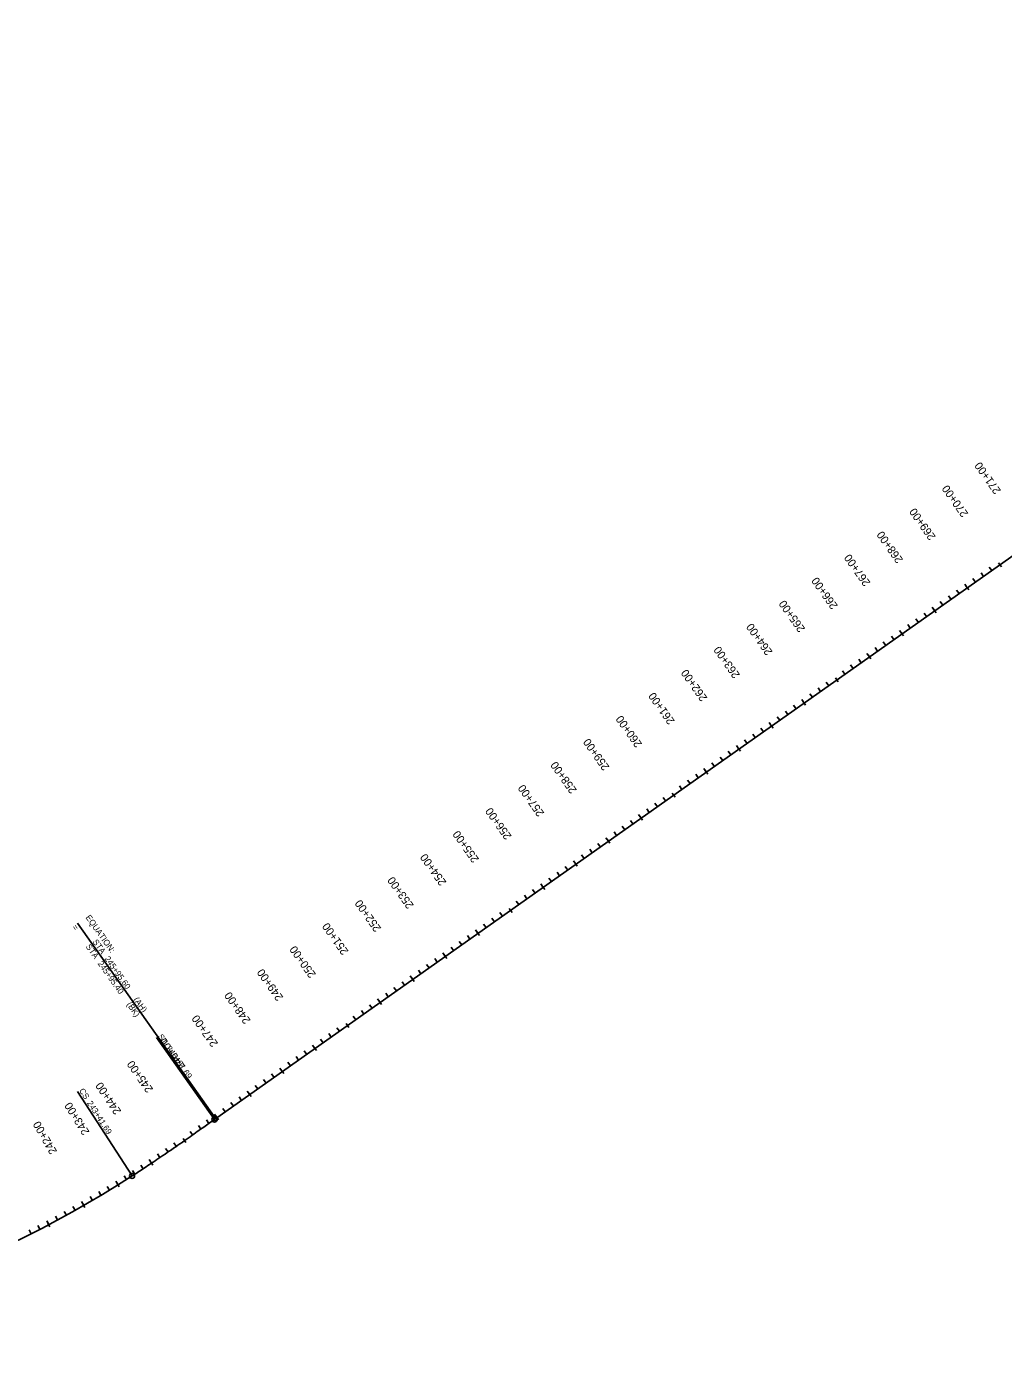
# Model space of a CAD drawing. Extents: x 22693007 to 22771804, y 6223023 to 6251673.
# Drawn here: x 22702871 to 22705317, y 6231587 to 6234910 of the extents above; entities that cross this region are included whole.
import ezdxf

# ---------------------------------------------------------------- set-up
doc = ezdxf.new("R2010")
doc.units = 0
for name, color, linetype in [('Default', 7, 'Continuous'), ('Draft_2', 7, 'Continuous'), ('NamedBoundary', 7, 'Continuous'), ('SheetBorder', 7, 'Continuous'), ('TextAlignment', 7, 'Continuous')]:
    doc.layers.add(name, color=color, linetype=linetype)

msp = doc.modelspace()

# ---------------------------------------------------------------- linework, layer by layer
at = {"layer": 'Default'}
msp.add_line((22703341, 6232172.5), (22707216.1, 6234910.4), dxfattribs=at)
msp.add_arc((22701585.2, 6234441), 2865, 274.9322, 302.7427, dxfattribs=at)
msp.add_open_spline([(22703134.8, 6232031.3), (22703143.6, 6232036.9), (22703161, 6232048.3), (22703195.7, 6232071.3), (22703238.7, 6232100.7), (22703281.4, 6232130.5), (22703315.5, 6232154.5), (22703332.5, 6232166.5), (22703341, 6232172.5)], degree=3, dxfattribs=at)
at = {"layer": 'Draft_2'}
for p, q in [((22705304.2, 6233567.1), (22705311.3, 6233557.1)), ((22705226.1, 6233504.4), (22705219.8, 6233513.3)), ((22705144.4, 6233446.7), (22705138.1, 6233455.6)), ((22705062.8, 6233389), (22705056.5, 6233397.9)), ((22704981.1, 6233331.3), (22704974.8, 6233340.2)), ((22704895.9, 6233278.6), (22704902.9, 6233268.6)), ((22704817.7, 6233215.9), (22704811.4, 6233224.8)), ((22704736.1, 6233158.2), (22704729.8, 6233167.1)), ((22704654.4, 6233100.5), (22704648.1, 6233109.4)), ((22704572.7, 6233042.8), (22704566.4, 6233051.7)), ((22704487.5, 6232990.1), (22704494.6, 6232980.1)), ((22704409.4, 6232927.4), (22704403.1, 6232936.3)), ((22704327.7, 6232869.6), (22704321.4, 6232878.6)), ((22704246, 6232811.9), (22704239.7, 6232820.9)), ((22704164.4, 6232754.2), (22704158.1, 6232763.2)), ((22704079.2, 6232701.5), (22704086.2, 6232691.5)), ((22704001, 6232638.8), (22703994.7, 6232647.7)), ((22703919.4, 6232581.1), (22703913.1, 6232590)), ((22703837.7, 6232523.4), (22703831.4, 6232532.3)), ((22703756, 6232465.7), (22703749.7, 6232474.6)), ((22703670.8, 6232413), (22703677.9, 6232403)), ((22703592.7, 6232350.3), (22703586.4, 6232359.2)), ((22703511, 6232292.6), (22703504.7, 6232301.5)), ((22703429.3, 6232234.9), (22703423, 6232243.8)), ((22703347.7, 6232177.2), (22703341.4, 6232186.1)), ((22703262.5, 6232124.8), (22703269.5, 6232114.7)), ((22703183.5, 6232063.3), (22703177.5, 6232072.3)), ((22703099.6, 6232009), (22703093.8, 6232018.2)), ((22703013.8, 6231957.6), (22703008.3, 6231967.1)), ((22702926.2, 6231909.3), (22702921.1, 6231918.9))]:
    msp.add_line(p, q, dxfattribs=at)
at = {"layer": 'NamedBoundary'}
msp.add_line((22703341, 6232172.5), (22707216.1, 6234910.4), dxfattribs=at)
msp.add_arc((22701585.2, 6234441), 2865, 274.9322, 302.7427, dxfattribs=at)
msp.add_open_spline([(22703134.8, 6232031.3), (22703143.6, 6232036.9), (22703161, 6232048.3), (22703195.7, 6232071.3), (22703238.7, 6232100.7), (22703281.4, 6232130.5), (22703315.5, 6232154.5), (22703332.5, 6232166.5), (22703341, 6232172.5)], degree=3, dxfattribs=at)
at = {"layer": 'SheetBorder'}
for p, q in [((22705266.9, 6233533.2), (22705260.6, 6233542.2)), ((22705287.4, 6233547.7), (22705281.1, 6233556.6)), ((22705304.2, 6233567.1), (22705311.3, 6233557.1)), ((22705222.6, 6233509.4), (22705229.6, 6233499.4)), ((22705246.5, 6233518.8), (22705240.2, 6233527.7)), ((22705185.3, 6233475.5), (22705179, 6233484.5)), ((22705205.7, 6233490), (22705199.4, 6233498.9)), ((22705124, 6233432.3), (22705117.7, 6233441.2)), ((22705140.9, 6233451.7), (22705148, 6233441.7)), ((22705164.8, 6233461.1), (22705158.5, 6233470)), ((22705083.2, 6233403.4), (22705076.9, 6233412.3)), ((22705103.6, 6233417.8), (22705097.3, 6233426.8)), ((22705042.3, 6233374.6), (22705036, 6233383.5)), ((22705059.2, 6233394), (22705066.3, 6233384)), ((22705001.5, 6233345.7), (22704995.2, 6233354.6)), ((22705021.9, 6233360.1), (22705015.6, 6233369)), ((22704940.3, 6233302.4), (22704933.9, 6233311.3)), ((22704960.7, 6233316.9), (22704954.4, 6233325.8)), ((22704977.6, 6233336.3), (22704984.6, 6233326.3)), ((22704895.9, 6233278.6), (22704902.9, 6233268.6)), ((22704919.8, 6233288), (22704913.5, 6233296.9)), ((22704838.2, 6233230.3), (22704831.9, 6233239.2)), ((22704858.6, 6233244.7), (22704852.3, 6233253.6)), ((22704879, 6233259.1), (22704872.7, 6233268.1)), ((22704797.3, 6233201.4), (22704791, 6233210.4)), ((22704814.2, 6233220.9), (22704821.3, 6233210.9)), ((22704756.5, 6233172.6), (22704750.2, 6233181.5)), ((22704776.9, 6233187), (22704770.6, 6233195.9)), ((22704715.7, 6233143.7), (22704709.4, 6233152.7)), ((22704732.5, 6233163.2), (22704739.6, 6233153.2)), ((22704650.9, 6233105.5), (22704657.9, 6233095.5)), ((22704674.8, 6233114.9), (22704668.5, 6233123.8)), ((22704695.2, 6233129.3), (22704688.9, 6233138.2)), ((22704613.6, 6233071.6), (22704607.3, 6233080.5)), ((22704634, 6233086), (22704627.7, 6233095)), ((22704569.2, 6233047.8), (22704576.3, 6233037.8)), ((22704593.1, 6233057.2), (22704586.8, 6233066.1)), ((22704511.5, 6232999.5), (22704505.2, 6233008.4)), ((22704531.9, 6233013.9), (22704525.6, 6233022.8)), ((22704552.3, 6233028.3), (22704546, 6233037.3)), ((22704470.6, 6232970.6), (22704464.3, 6232979.5)), ((22704487.5, 6232990.1), (22704494.6, 6232980.1)), ((22704429.8, 6232941.8), (22704423.5, 6232950.7)), ((22704450.2, 6232956.2), (22704443.9, 6232965.1)), ((22704368.5, 6232898.5), (22704362.2, 6232907.4)), ((22704389, 6232912.9), (22704382.7, 6232921.8)), ((22704405.9, 6232932.3), (22704412.9, 6232922.4)), ((22704324.2, 6232874.6), (22704331.2, 6232864.6)), ((22704348.1, 6232884.1), (22704341.8, 6232893)), ((22704286.9, 6232840.8), (22704280.6, 6232849.7)), ((22704307.3, 6232855.2), (22704301, 6232864.1)), ((22704225.6, 6232797.5), (22704219.3, 6232806.4)), ((22704242.5, 6232816.9), (22704249.6, 6232806.9)), ((22704266.5, 6232826.4), (22704260.2, 6232835.3)), ((22704184.8, 6232768.7), (22704178.5, 6232777.6)), ((22704205.2, 6232783.1), (22704198.9, 6232792)), ((22704144, 6232739.8), (22704137.7, 6232748.7)), ((22704160.8, 6232759.2), (22704167.9, 6232749.2)), ((22704103.1, 6232711), (22704096.8, 6232719.9)), ((22704123.5, 6232725.4), (22704117.2, 6232734.3)), ((22704041.9, 6232667.7), (22704035.6, 6232676.6)), ((22704062.3, 6232682.1), (22704056, 6232691)), ((22704079.2, 6232701.5), (22704086.2, 6232691.5)), ((22703997.5, 6232643.8), (22704004.6, 6232633.8)), ((22704021.4, 6232653.3), (22704015.1, 6232662.2)), ((22703960.2, 6232610), (22703953.9, 6232618.9)), ((22703980.6, 6232624.4), (22703974.3, 6232633.3)), ((22703898.9, 6232566.7), (22703892.6, 6232575.6)), ((22703915.8, 6232586.1), (22703922.9, 6232576.1)), ((22703939.8, 6232595.6), (22703933.5, 6232604.5)), ((22703858.1, 6232537.8), (22703851.8, 6232546.8)), ((22703878.5, 6232552.3), (22703872.2, 6232561.2)), ((22703817.3, 6232509), (22703811, 6232517.9)), ((22703834.2, 6232528.4), (22703841.2, 6232518.4)), ((22703776.4, 6232480.1), (22703770.1, 6232489.1)), ((22703796.8, 6232494.6), (22703790.5, 6232503.5)), ((22703715.2, 6232436.9), (22703708.9, 6232445.8)), ((22703735.6, 6232451.3), (22703729.3, 6232460.2)), ((22703752.5, 6232470.7), (22703759.5, 6232460.7)), ((22703670.8, 6232413), (22703677.9, 6232403)), ((22703694.8, 6232422.4), (22703688.5, 6232431.4)), ((22703633.5, 6232379.2), (22703627.2, 6232388.1)), ((22703653.9, 6232393.6), (22703647.6, 6232402.5)), ((22703572.3, 6232335.9), (22703565.9, 6232344.8)), ((22703589.1, 6232355.3), (22703596.2, 6232345.3)), ((22703613.1, 6232364.7), (22703606.8, 6232373.7)), ((22703531.4, 6232307), (22703525.1, 6232316)), ((22703551.8, 6232321.5), (22703545.5, 6232330.4)), ((22703490.6, 6232278.2), (22703484.3, 6232287.1)), ((22703507.5, 6232297.6), (22703514.5, 6232287.6)), ((22703449.7, 6232249.3), (22703443.4, 6232258.2)), ((22703470.2, 6232263.8), (22703463.9, 6232272.7)), ((22703388.5, 6232206.1), (22703382.2, 6232215)), ((22703408.9, 6232220.5), (22703402.6, 6232229.4)), ((22703425.8, 6232239.9), (22703432.9, 6232229.9)), ((22703344.1, 6232182.2), (22703351.2, 6232172.2)), ((22703368.1, 6232191.6), (22703361.8, 6232200.5)), ((22703286.5, 6232134.1), (22703280.2, 6232143)), ((22703307, 6232148.5), (22703300.7, 6232157.4)), ((22703327.4, 6232162.9), (22703321.1, 6232171.8)), ((22703245.5, 6232105.5), (22703239.3, 6232114.5)), ((22703262.5, 6232124.8), (22703269.5, 6232114.7)), ((22703204.3, 6232077.2), (22703198.1, 6232086.3)), ((22703224.9, 6232091.3), (22703218.8, 6232100.3)), ((22703141.8, 6232035.8), (22703135.8, 6232044.9)), ((22703162.7, 6232049.4), (22703156.7, 6232058.5)), ((22703180.1, 6232068.3), (22703186.9, 6232058.2)), ((22703096.3, 6232014.2), (22703102.8, 6232003.8)), ((22703120.7, 6232022.3), (22703114.9, 6232031.5)), ((22703035.4, 6231970.2), (22703029.9, 6231979.6)), ((22703056.9, 6231982.9), (22703051.3, 6231992.3)), ((22703078.3, 6231995.8), (22703072.6, 6232005.2)), ((22702970.2, 6231933), (22702964.9, 6231942.6)), ((22702992, 6231945.2), (22702986.7, 6231954.7)), ((22703010.7, 6231962.9), (22703016.8, 6231952.3)), ((22702923.4, 6231914.7), (22702929.1, 6231903.9)), ((22702948.3, 6231921.1), (22702943.1, 6231930.7)), ((22702881.8, 6231886.2), (22702876.9, 6231896)), ((22702904.1, 6231897.7), (22702899.1, 6231907.3))]:
    msp.add_line(p, q, dxfattribs=at)
at = {"layer": 'TextAlignment'}
for p, q in [((22703344.1, 6232174.7), (22702997.8, 6232664.7)), ((22702997.8, 6232664.7), (22702997.8, 6232664.7)), ((22703341, 6232172.5), (22703195.6, 6232378.3)), ((22703195.6, 6232378.3), (22703195.6, 6232378.3)), ((22703134.8, 6232031.3), (22702998.5, 6232243.2)), ((22702998.5, 6232243.2), (22702998.5, 6232243.2)), ((22703134.8, 6232031.3), (22702998.5, 6232243.2)), ((22702998.5, 6232243.2), (22702998.5, 6232243.2))]:
    msp.add_line(p, q, dxfattribs=at)
for centre, radius in [((22703341, 6232172.5), 6.24), ((22703344.1, 6232174.7), 5.34), ((22703134.8, 6232031.3), 6.24), ((22703134.8, 6232031.3), 6.24)]:
    msp.add_circle(centre, radius, dxfattribs=at)

# ---------------------------------------------------------------- texts
at = {"layer": 'Draft_2'}
for s, rotation, p in [('270+00', 125.2425, (22705229.4, 6233690.4)), ('265+00', 125.2425, (22704821, 6233401.9)), ('260+00', 125.2425, (22704412.7, 6233113.3)), ('255+00', 125.2425, (22704004.3, 6232824.8)), ('250+00', 125.2425, (22703596, 6232536.3)), ('245+00', 124.9063, (22703188.4, 6232248.5))]:
    msp.add_text(s, height=20.04, rotation=rotation, dxfattribs=at).set_placement(p)
at = {"layer": 'SheetBorder'}
for s, rotation, p in [('271+00', 125.2425, (22705311.1, 6233748.1)), ('270+00', 125.2425, (22705229.4, 6233690.4)), ('269+00', 125.2425, (22705147.7, 6233632.7)), ('268+00', 125.2425, (22705066.1, 6233575)), ('267+00', 125.2425, (22704984.4, 6233517.3)), ('266+00', 125.2425, (22704902.7, 6233459.6)), ('265+00', 125.2425, (22704821, 6233401.9)), ('264+00', 125.2425, (22704739.4, 6233344.2)), ('263+00', 125.2425, (22704657.7, 6233286.5)), ('262+00', 125.2425, (22704576, 6233228.8)), ('261+00', 125.2425, (22704494.4, 6233171)), ('260+00', 125.2425, (22704412.7, 6233113.3)), ('259+00', 125.2425, (22704331, 6233055.6)), ('258+00', 125.2425, (22704249.3, 6232997.9)), ('257+00', 125.2425, (22704167.7, 6232940.2)), ('256+00', 125.2425, (22704086, 6232882.5)), ('255+00', 125.2425, (22704004.3, 6232824.8)), ('254+00', 125.2425, (22703922.7, 6232767.1)), ('253+00', 125.2425, (22703841, 6232709.4)), ('252+00', 125.2425, (22703759.3, 6232651.7)), ('251+00', 125.2425, (22703677.6, 6232594)), ('250+00', 125.2425, (22703596, 6232536.3)), ('249+00', 125.2425, (22703514.3, 6232478.6)), ('248+00', 125.2425, (22703432.6, 6232420.9)), ('247+00', 125.2425, (22703351, 6232363.2)), ('246+00', 125.2425, (22703269.3, 6232305.5)), ('245+00', 124.9063, (22703188.4, 6232248.5)), ('244+00', 123.7728, (22703108.5, 6232193.5)), ('243+00', 121.9089, (22703028.8, 6232141.6)), ('242+00', 119.9091, (22702947.7, 6232092.6))]:
    msp.add_text(s, height=20.04, rotation=rotation, dxfattribs=at).set_placement(p)
at = {"layer": 'TextAlignment'}
for s, rotation, p in [('EQUATION:', 305.2425, (22703017.7, 6232678.7)), ('=', 305.2425, (22702983.4, 6232654.5)), ('STA ', 305.2425, (22703018, 6232605.5)), ('STA ', 305.2425, (22703035.2, 6232617.6)), ('245+95.60', 305.2425, (22703065.1, 6232575.2)), ('245+95.40', 305.2425, (22703048, 6232563.1)), ('(AH)', 305.2425, (22703137.5, 6232472.8)), ('(BK)', 305.2425, (22703120.3, 6232460.7)), ('ST', 305.2425, (22703198.3, 6232380.2)), ('245+91.69', 305.2425, (22703219.1, 6232350.8)), ('CS', 302.7427, (22703001.3, 6232245)), ('CS', 302.7427, (22703001.3, 6232245)), ('243+41.69', 302.7427, (22703021.3, 6232213.8)), ('243+41.69', 302.7427, (22703021.3, 6232213.8))]:
    msp.add_text(s, height=15, rotation=rotation, dxfattribs=at).set_placement(p)

doc.saveas('drawing.dxf')
